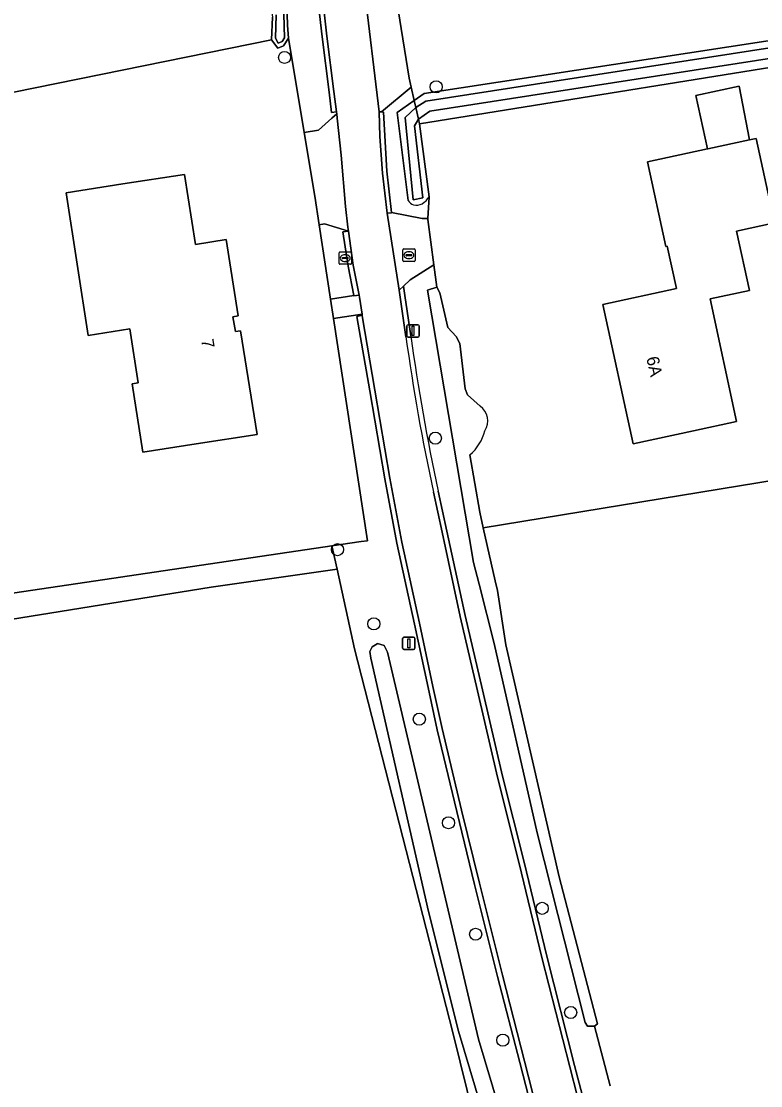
# Model space of a CAD drawing. Extents: x 162510 to 163918, y 388494 to 389774.
# Drawn here: x 163110.5 to 163170.3, y 389509.4 to 389595.4 of the extents above; entities that cross this region are included whole.
import ezdxf

# ---------------------------------------------------------------- set-up
doc = ezdxf.new("R2010")
doc.units = 0
for name, color, linetype in [('IMGEO_Afsluitpaal', 7, 'Continuous'), ('IMGEO_Boom', 7, 'Continuous'), ('IMGEO_Bouwland', 7, 'Continuous'), ('IMGEO_Brandkraan', 7, 'Continuous'), ('IMGEO_Erf', 7, 'Continuous'), ('IMGEO_Grasland_agrarisch', 7, 'Continuous'), ('IMGEO_Grasland_overig', 7, 'Continuous'), ('IMGEO_Groenvoorziening', 7, 'Continuous'), ('IMGEO_Oever', 7, 'Continuous'), ('IMGEO_Pand', 7, 'Continuous'), ('IMGEO_Pand_nummerreeks', 7, 'Continuous'), ('IMGEO_Rijbaan_lokaal_gesloten', 7, 'Continuous'), ('IMGEO_Rijbaan_lokaal_halfverhard', 7, 'Continuous'), ('IMGEO_Rijbaan_lokaal_open', 7, 'Continuous'), ('IMGEO_Rioolput', 7, 'Continuous'), ('IMGEO_Verkeersbordpaal', 7, 'Continuous'), ('IMGEO_Voetpad_open', 7, 'Continuous'), ('IMGEO_Waterloop', 7, 'Continuous')]:
    doc.layers.add(name, color=color, linetype=linetype)

msp = doc.modelspace()

# ---------------------------------------------------------------- linework, layer by layer
at = {"layer": 'IMGEO_Afsluitpaal'}
for p, q in [((163141.67, 389569.989), (163141.67, 389570.789)), ((163141.67, 389570.789), (163141.67, 389569.989)), ((163141.77, 389570.889), (163142.56, 389570.889)), ((163142.56, 389570.889), (163141.77, 389570.889)), ((163142.66, 389570.789), (163142.66, 389569.989)), ((163142.66, 389569.989), (163142.66, 389570.789)), ((163142.56, 389569.889), (163141.77, 389569.889)), ((163141.77, 389569.889), (163142.56, 389569.889))]:
    msp.add_line(p, q, dxfattribs=at)
msp.add_lwpolyline([(163142.09, 389570.764), (163142.24, 389570.764), (163142.24, 389570.014), (163142.09, 389570.014), (163142.09, 389570.764)], dxfattribs=at)
for centre, start, end in [((163141.77, 389570.789), 90, 180), ((163141.77, 389570.789), 90, 180), ((163142.56, 389570.789), 0, 90), ((163142.56, 389570.789), 360, 90), ((163141.77, 389569.989), 180, 270), ((163141.77, 389569.989), 180, 270), ((163142.56, 389569.989), 270, 0), ((163142.56, 389569.989), 270, 0)]:
    msp.add_arc(centre, 0.1, start, end, dxfattribs=at)
at = {"layer": 'IMGEO_Boom'}
for centre in [(163131.792, 389592.486), (163144.039, 389590.102), (163143.976, 389561.724), (163136.071, 389552.716), (163139, 389546.719), (163142.678, 389539.015), (163145.036, 389530.651), (163152.616, 389523.734), (163147.231, 389521.64), (163154.915, 389515.315), (163149.429, 389513.082)]:
    msp.add_circle(centre, 0.489, dxfattribs=at)
at = {"layer": 'IMGEO_Bouwland'}
msp.add_lwpolyline([(163081.431, 389571.505), (163036.713, 389569.507), (163036.922, 389568.463), (163034.881, 389568.403), (163038.378, 389551.874), (163041.389, 389540.203), (163045.337, 389519.553), (163052.453, 389485.976), (163058.338, 389486.211), (163065.742, 389486.647), (163069.57, 389487.128), (163075.689, 389486.797), (163079.708, 389487.203), (163100.597, 389488.503), (163120.69, 389490.419), (163133.944, 389491.791), (163150.042, 389494.851), (163145.402, 389513.689), (163141.615, 389528.41), (163137.44, 389544.706), (163136.047, 389551.139), (163125.857, 389549.679), (163092.552, 389544.325), (163089.105, 389543.766)], close=True, dxfattribs=at)
at = {"layer": 'IMGEO_Brandkraan'}
for p, q in [((163136.193, 389575.842), (163136.193, 389576.694)), ((163136.268, 389576.768), (163137.12, 389576.768)), ((163136.452, 389576.262), (163136.452, 389576.274)), ((163136.89, 389576.225), (163136.492, 389576.225)), ((163136.495, 389576.311), (163136.893, 389576.311)), ((163136.681, 389576.548), (163136.706, 389576.548)), ((163136.936, 389576.274), (163136.936, 389576.262)), ((163137.194, 389576.694), (163137.194, 389575.842)), ((163137.12, 389575.768), (163136.268, 389575.768)), ((163136.704, 389575.988), (163136.679, 389575.988))]:
    msp.add_line(p, q, dxfattribs=at)
for points in [[(163136.193, 389575.842), (163136.193, 389576.694)], [(163136.268, 389576.768), (163137.12, 389576.768)], [(163137.194, 389576.694), (163137.194, 389575.842)], [(163137.12, 389575.768), (163136.268, 389575.768)]]:
    msp.add_lwpolyline(points, dxfattribs=at)
for centre, radius, start, end in [((163136.27, 389576.692), 0.0765, 91.55205, 178.44795), ((163136.27, 389576.692), 0.0765, 91.55205, 178.44795), ((163136.492, 389576.271), 0.0403, 85.87752, 175.75265), ((163136.489, 389576.261), 0.0366, 178.93798, 274.71019), ((163136.893, 389576.268), 0.043, 264.86636, 352.45326), ((163136.897, 389576.273), 0.0386, 1.73085, 96.63898), ((163137.118, 389576.692), 0.0765, 1.55205, 88.44795), ((163137.118, 389576.692), 0.0765, 1.55205, 88.44795), ((163136.27, 389575.844), 0.0765, 181.55205, 268.44795), ((163136.27, 389575.844), 0.0765, 181.55205, 268.44795), ((163137.118, 389575.844), 0.0765, 271.55205, 358.44795), ((163137.118, 389575.844), 0.0765, 271.55205, 358.44795)]:
    msp.add_arc(centre, radius, start, end, dxfattribs=at)
for centre, major_axis, ratio, start_param, end_param in [((163136.68, 389576.268), (-0.387, 0.002), 0.722429, 4.712389, 7.853982), ((163136.705, 389576.268), (-0.39, 0.002), 0.717154, 1.570796, 4.712389)]:
    msp.add_ellipse(centre, major_axis=major_axis, ratio=ratio, start_param=start_param, end_param=end_param, dxfattribs=at)
at = {"layer": 'IMGEO_Erf'}
for points in [[(163146.776, 389560.376), (163147.559, 389555.746), (163147.85, 389554.465), (163200.467, 389563.084), (163209.162, 389564.768), (163211.121, 389565.147), (163210.605, 389567.919), (163211.953, 389568.291), (163210.994, 389575.221), (163208.337, 389574.958), (163206.563, 389587.551), (163202.535, 389611.212), (163185.361, 389663.193), (163183.199, 389670.235), (163182.976, 389670.167), (163189.652, 389648.224), (163198.162, 389622.433), (163197.592, 389622.245), (163189.08, 389648.043), (163182.625, 389669.258)], [(163137.903, 389615.424), (163141.862, 389590.82), (163142.032, 389590.074), (163142.273, 389589.016), (163143.068, 389589.581), (163201.297, 389598.514)], [(163201.383, 389596.57), (163184.867, 389593.87), (163185.299, 389590.871), (163179.29, 389590.006), (163178.867, 389592.946), (163142.703, 389587.125), (163143.463, 389581.223), (163143.376, 389579.476), (163143.371, 389579.381), (163143.861, 389575.722), (163144.086, 389573.93), (163144.327, 389573.462), (163144.976, 389570.666), (163145.666, 389569.948), (163145.953, 389569.366), (163146.391, 389565.701), (163146.582, 389565.22), (163147.61, 389564.317)]]:
    msp.add_lwpolyline(points, dxfattribs=at)
for points in [[(163135.605, 389553.015), (163137.969, 389553.364), (163138.48, 389553.44), (163135.741, 389571.383), (163135.501, 389572.957), (163134.583, 389578.971), (163134.232, 389581.269), (163133.369, 389586.428), (163132.097, 389594.034), (163131.711, 389593.428), (163131.252, 389593.229), (163130.743, 389593.913), (163099.541, 389587.586), (163095.489, 389586.851), (163101.431, 389547.961)], [(163165.975, 389585.088), (163165.041, 389589.4), (163168.544, 389590.158), (163169.364, 389585.821), (163169.917, 389585.941), (163171.396, 389579.109), (163168.327, 389578.445), (163169.361, 389573.666), (163166.185, 389572.979), (163168.33, 389563.071), (163164.841, 389562.316), (163159.954, 389561.258), (163157.514, 389572.532), (163163.455, 389573.818), (163162.715, 389577.238), (163162.598, 389577.213), (163161.121, 389584.037)], [(163123.699, 389583.033), (163124.584, 389577.378), (163127.071, 389577.78), (163128.042, 389571.601), (163127.606, 389571.529), (163127.811, 389570.327), (163128.24, 389570.406), (163129.579, 389562.03), (163124.639, 389561.261), (163120.343, 389560.591), (163119.481, 389566.125), (163119.966, 389566.201), (163119.288, 389570.554), (163115.922, 389570.03), (163114.129, 389581.542), (163118.724, 389582.259)]]:
    msp.add_lwpolyline(points, close=True, dxfattribs=at)
for centre, radius, start, end in [((163146.674, 389563.106), 1.531, 329.07671, 52.29416), ((163144.277, 389563.282), 3.833, 310.68755, 345.44493)]:
    msp.add_arc(centre, radius, start, end, dxfattribs=at)
at = {"layer": 'IMGEO_Grasland_agrarisch'}
for points in [[(162938.565, 389557.01), (163031.158, 389573.647), (163038.447, 389575.02), (163070.03, 389580.97), (163070.105, 389582.244), (163086.403, 389585.202), (163088.57, 389585.595), (163095.489, 389586.851), (163099.541, 389587.586), (163130.743, 389593.913), (163130.817, 389595.747)], [(163302.524, 389566.919), (163271.821, 389559.091), (163236.385, 389551.103), (163216.962, 389546.983), (163214.666, 389550.733), (163209.162, 389564.768), (163200.467, 389563.084), (163147.85, 389554.465), (163148.821, 389550.197), (163149, 389549.411), (163149.675, 389545.037), (163153.995, 389526.272), (163157.089, 389514.412), (163156.831, 389514.217), (163158.114, 389509.391)]]:
    msp.add_lwpolyline(points, dxfattribs=at)
at = {"layer": 'IMGEO_Grasland_overig'}
for points in [[(163131.988, 389595.99), (163132.038, 389595.088), (163132.097, 389594.034), (163133.369, 389586.428), (163134.528, 389586.609), (163135.61, 389587.567), (163136.009, 389587.92), (163135.989, 389588.081), (163135.592, 389588.034), (163135.386, 389589.682), (163134.821, 389594.161), (163134.055, 389600.943)], [(163158.114, 389509.391), (163156.831, 389514.217), (163156.275, 389514.216), (163156.074, 389514.497), (163152.198, 389529.843), (163148.741, 389545.124), (163147.511, 389549.919), (163147.062, 389551.67), (163143.333, 389573.672), (163144.086, 389573.93), (163143.861, 389575.722), (163141.938, 389574.52), (163141.403, 389574.011), (163141.519, 389573.248), (163141.99, 389569.979)], [(163144.208, 389557.436), (163144.911, 389554.204), (163146.381, 389547.392), (163147.778, 389541.399), (163149.397, 389534.42), (163151.145, 389527.457), (163152.981, 389519.863), (163155.232, 389511.027), (163155.857, 389508.596), (163156.989, 389504.138), (163156.58, 389504.033), (163157.183, 389501.707), (163158.324, 389500), (163159.376, 389498.426), (163161.227, 389491.733), (163161.913, 389489.267), (163162.855, 389482.594), (163163.024, 389482.162), (163163.358, 389482.274), (163163.998, 389480.594), (163165.073, 389477.775), (163167.095, 389472.533)]]:
    msp.add_lwpolyline(points, dxfattribs=at)
for points in [[(163136.943, 389578.443), (163135.007, 389579.042), (163134.583, 389578.971), (163135.501, 389572.957), (163137.394, 389573.255), (163136.94, 389575.625), (163136.492, 389578.38)], [(163094.295, 389546.906), (163092.161, 389546.361), (163092.552, 389544.325), (163125.857, 389549.679), (163136.047, 389551.139), (163135.605, 389553.015), (163101.431, 389547.961)]]:
    msp.add_lwpolyline(points, close=True, dxfattribs=at)
msp.add_arc((163317.446, 389594.538), 177.166, 187.96792, 192.08816, dxfattribs=at)
at = {"layer": 'IMGEO_Groenvoorziening'}
for points in [[(163142.273, 389589.016), (163142.032, 389590.074), (163139.61, 389588.085), (163139.784, 389588.073), (163140.065, 389583.296), (163140.425, 389579.967), (163142.916, 389579.473), (163143.376, 389579.476), (163143.463, 389581.223)], [(163141.774, 389580.916), (163140.89, 389588.033), (163142.273, 389589.016)], [(163151.769, 389507.502), (163150.791, 389511.273), (163149.005, 389518.231), (163147.151, 389525.659), (163145.708, 389531.564), (163144.129, 389538.161), (163143.391, 389541.585), (163142.292, 389546.693), (163140.869, 389553.236), (163139.895, 389558.423), (163138.683, 389565.543), (163137.641, 389571.561), (163138.065, 389571.647), (163138.051, 389571.74), (163135.741, 389571.383), (163138.48, 389553.44), (163137.969, 389553.364), (163135.605, 389553.015), (163136.047, 389551.139), (163137.44, 389544.706), (163141.615, 389528.41), (163145.402, 389513.689), (163150.042, 389494.851)], [(163150.884, 389497.95), (163150.592, 389498.209), (163150.426, 389498.501), (163149.969, 389500), (163145.858, 389513.801), (163143.43, 389523.472), (163138.762, 389543.954), (163138.691, 389544.487), (163138.872, 389544.867), (163139.265, 389545.116), (163139.306, 389545.142), (163139.838, 389544.96), (163140.112, 389544.424), (163147.453, 389513.152), (163151.385, 389500)]]:
    msp.add_lwpolyline(points, dxfattribs=at)
for centre, radius, start, end in [((163142.448, 389581.353), 0.804, 212.95584, 252.67475), ((163142.464, 389581.54), 0.988, 255.04432, 297.10059), ((163142.004, 389582.099), 1.702, 302.3257, 329.0151)]:
    msp.add_arc(centre, radius, start, end, dxfattribs=at)
at = {"layer": 'IMGEO_Oever'}
msp.add_lwpolyline([(163129.208, 389611.859), (163125.403, 389629.439), (163123.905, 389635.216), (163122.598, 389639.595), (163121.03, 389643.956), (163120.563, 389643.837), (163120.085, 389643.716), (163122.348, 389637.109), (163124.168, 389630.542), (163127.314, 389615.888), (163129.494, 389604.011), (163130.817, 389595.747), (163130.743, 389593.913), (163131.252, 389593.229), (163131.711, 389593.428), (163132.097, 389594.034), (163132.038, 389595.088), (163131.988, 389595.99)], close=True, dxfattribs=at)
for points in [[(163201.297, 389598.514), (163143.068, 389589.581), (163142.273, 389589.016), (163142.407, 389588.427), (163143.22, 389588.953), (163174.848, 389593.847), (163200.912, 389597.997)], [(163201.02, 389597.159), (163174.979, 389593.013), (163143.527, 389588.146), (163142.616, 389587.508), (163142.703, 389587.125), (163178.867, 389592.946), (163178.858, 389593.005), (163184.867, 389593.87), (163201.383, 389596.57), (163201.297, 389598.514)], [(163131.722, 389595.983), (163131.793, 389594.067), (163131.59, 389593.779), (163131.277, 389593.646), (163131.057, 389594.03), (163131.101, 389595.934)], [(163142.703, 389587.125), (163142.616, 389587.508), (163142.291, 389586.966), (163142.951, 389581.13), (163142.171, 389580.988), (163141.532, 389587.63), (163142.407, 389588.427), (163142.273, 389589.016), (163140.89, 389588.033), (163141.774, 389580.916)], [(163143.463, 389581.223), (163142.703, 389587.125)]]:
    msp.add_lwpolyline(points, dxfattribs=at)
for centre, radius, start, end in [((163142.448, 389581.353), 0.804, 212.95584, 252.67475), ((163142.464, 389581.54), 0.988, 255.04432, 297.10059), ((163142.004, 389582.099), 1.702, 302.3257, 329.0151)]:
    msp.add_arc(centre, radius, start, end, dxfattribs=at)
at = {"layer": 'IMGEO_Pand'}
for points in [[(163165.041, 389589.4), (163165.975, 389585.088), (163166.008, 389585.095), (163169.364, 389585.821), (163168.544, 389590.158)], [(163169.361, 389573.666), (163168.327, 389578.445), (163171.396, 389579.109), (163169.917, 389585.941), (163169.364, 389585.821), (163166.008, 389585.095), (163165.975, 389585.088), (163161.121, 389584.037), (163162.598, 389577.213), (163162.715, 389577.238), (163163.455, 389573.818), (163157.514, 389572.532), (163159.954, 389561.258), (163164.841, 389562.316), (163168.33, 389563.071), (163166.185, 389572.979)], [(163124.639, 389561.261), (163129.579, 389562.03), (163128.24, 389570.406), (163127.811, 389570.327), (163127.606, 389571.529), (163128.042, 389571.601), (163127.071, 389577.78), (163124.584, 389577.378), (163123.699, 389583.033), (163118.724, 389582.259), (163114.129, 389581.542), (163115.922, 389570.03), (163119.288, 389570.554), (163119.966, 389566.201), (163119.481, 389566.125), (163120.343, 389560.591)]]:
    msp.add_lwpolyline(points, close=True, dxfattribs=at)
at = {"layer": 'IMGEO_Rijbaan_lokaal_gesloten'}
for points in [[(163141.594, 389569.922), (163141.053, 389573.687), (163140.094, 389579.9), (163139.708, 389583.144), (163139.501, 389586.097), (163139.435, 389588.098), (163138.216, 389598.189), (163137.336, 389604.367), (163136.223, 389611.66), (163135.209, 389617.098), (163135.203, 389617.129), (163135.046, 389618.008), (163134.841, 389619.053), (163133.209, 389626.239)], [(163134.452, 389600.988), (163135.218, 389594.211), (163135.783, 389589.732), (163135.989, 389588.081), (163136.009, 389587.92), (163136.053, 389587.568), (163136.359, 389584.6), (163136.722, 389580.439), (163136.898, 389578.763), (163136.943, 389578.443), (163137.333, 389575.702), (163137.807, 389573.277), (163137.838, 389573.12), (163138.051, 389571.74), (163138.065, 389571.647), (163138.072, 389571.603), (163139.077, 389565.61), (163140.288, 389558.497), (163141.26, 389553.321), (163142.683, 389546.777), (163143.782, 389541.669), (163144.518, 389538.254), (163146.097, 389531.659), (163147.539, 389525.756), (163149.392, 389518.33), (163151.178, 389511.373), (163152.156, 389507.602)], [(163157.812, 389499.279), (163157.183, 389501.707), (163156.58, 389504.033), (163155.47, 389508.496), (163154.845, 389510.927), (163152.593, 389519.764), (163150.756, 389527.363), (163149.007, 389534.33), (163147.388, 389541.309), (163145.99, 389547.308), (163144.52, 389554.12), (163143.817, 389557.352)]]:
    msp.add_lwpolyline(points, dxfattribs=at)
msp.add_arc((163317.186, 389594.494), 177.303, 187.96607, 192.09201, dxfattribs=at)
at = {"layer": 'IMGEO_Rijbaan_lokaal_halfverhard'}
for points in [[(163129.617, 389624.501), (163130.847, 389619.293), (163131.78, 389614.905), (163132.904, 389609.133), (163133.517, 389605.201), (163134.055, 389600.943), (163134.821, 389594.161), (163135.386, 389589.682), (163135.592, 389588.034), (163135.989, 389588.081), (163135.783, 389589.732), (163135.218, 389594.211), (163134.452, 389600.988), (163133.914, 389605.251), (163133.299, 389609.195), (163132.173, 389614.981), (163131.238, 389619.376), (163130.006, 389624.593)], [(163141.403, 389574.011), (163141.053, 389573.687), (163141.594, 389569.922)], [(163141.99, 389569.979), (163141.519, 389573.248), (163141.403, 389574.011)], [(163152.156, 389507.602), (163151.178, 389511.373), (163149.392, 389518.33), (163147.539, 389525.756), (163146.097, 389531.659), (163144.518, 389538.254), (163143.782, 389541.669), (163142.683, 389546.777), (163141.26, 389553.321), (163140.288, 389558.497), (163139.077, 389565.61), (163138.072, 389571.603), (163138.065, 389571.647), (163137.641, 389571.561), (163138.683, 389565.543), (163139.895, 389558.423), (163140.869, 389553.236), (163142.292, 389546.693), (163143.391, 389541.585), (163144.129, 389538.161), (163145.708, 389531.564), (163147.151, 389525.659), (163149.005, 389518.231), (163150.791, 389511.273), (163151.769, 389507.502)], [(163143.817, 389557.352), (163144.52, 389554.12), (163145.99, 389547.308), (163147.388, 389541.309), (163149.007, 389534.33), (163150.756, 389527.363), (163152.593, 389519.764), (163154.845, 389510.927), (163155.47, 389508.496), (163156.58, 389504.033), (163156.989, 389504.138), (163155.857, 389508.596), (163155.232, 389511.027), (163152.981, 389519.863), (163151.145, 389527.457), (163149.397, 389534.42), (163147.778, 389541.399), (163146.381, 389547.392), (163144.911, 389554.204), (163144.208, 389557.436)]]:
    msp.add_lwpolyline(points, dxfattribs=at)
for points in [[(163139.784, 389588.073), (163139.61, 389588.085), (163139.435, 389588.098), (163139.501, 389586.097), (163139.708, 389583.144), (163140.094, 389579.9), (163140.429, 389579.931), (163140.425, 389579.967), (163140.065, 389583.296)], [(163136.943, 389578.443), (163136.492, 389578.38), (163136.94, 389575.625), (163137.394, 389573.255), (163137.398, 389573.232), (163137.807, 389573.277), (163137.333, 389575.702)]]:
    msp.add_lwpolyline(points, close=True, dxfattribs=at)
for centre, radius, start, end in [((163317.186, 389594.494), 177.303, 187.96607, 192.09201), ((163317.446, 389594.538), 177.166, 187.96792, 192.08816)]:
    msp.add_arc(centre, radius, start, end, dxfattribs=at)
at = {"layer": 'IMGEO_Rijbaan_lokaal_open'}
for points in [[(163137.903, 389615.424), (163137.442, 389617.529), (163135.597, 389617.199), (163135.203, 389617.129), (163135.209, 389617.098), (163136.223, 389611.66), (163137.336, 389604.367), (163138.216, 389598.189), (163139.435, 389588.098), (163139.61, 389588.085), (163142.032, 389590.074), (163141.862, 389590.82)], [(163136.009, 389587.92), (163135.61, 389587.567), (163134.528, 389586.609), (163133.369, 389586.428), (163134.232, 389581.269), (163134.583, 389578.971), (163135.007, 389579.042), (163136.943, 389578.443), (163136.898, 389578.763), (163136.722, 389580.439), (163136.359, 389584.6), (163136.053, 389587.568)], [(163143.371, 389579.381), (163143.376, 389579.476), (163142.916, 389579.473), (163140.425, 389579.967), (163140.429, 389579.931), (163140.094, 389579.9), (163141.053, 389573.687), (163141.403, 389574.011), (163141.938, 389574.52), (163143.861, 389575.722)]]:
    msp.add_lwpolyline(points, close=True, dxfattribs=at)
at = {"layer": 'IMGEO_Rioolput'}
for p, q in [((163141.341, 389576.082), (163141.341, 389576.934)), ((163141.416, 389577.008), (163142.268, 389577.008)), ((163141.6, 389576.502), (163141.6, 389576.514)), ((163142.038, 389576.465), (163141.64, 389576.465)), ((163141.643, 389576.551), (163142.041, 389576.551)), ((163141.852, 389576.228), (163141.827, 389576.228)), ((163141.829, 389576.788), (163141.854, 389576.788)), ((163142.084, 389576.514), (163142.084, 389576.502)), ((163142.342, 389576.934), (163142.342, 389576.082)), ((163142.268, 389576.008), (163141.416, 389576.008))]:
    msp.add_line(p, q, dxfattribs=at)
for points in [[(163141.341, 389576.082), (163141.341, 389576.934)], [(163141.416, 389577.008), (163142.268, 389577.008)], [(163142.342, 389576.934), (163142.342, 389576.082)], [(163142.268, 389576.008), (163141.416, 389576.008)]]:
    msp.add_lwpolyline(points, dxfattribs=at)
for centre, radius, start, end in [((163141.418, 389576.932), 0.0765, 91.55205, 178.44795), ((163141.418, 389576.932), 0.0765, 91.55205, 178.44795), ((163141.64, 389576.511), 0.0403, 85.87752, 175.75265), ((163141.637, 389576.501), 0.0366, 178.93798, 274.71019), ((163142.041, 389576.508), 0.043, 264.86636, 352.45326), ((163142.045, 389576.513), 0.0386, 1.73085, 96.63898), ((163142.266, 389576.932), 0.0765, 1.55205, 88.44795), ((163142.266, 389576.932), 0.0765, 1.55205, 88.44795), ((163141.418, 389576.084), 0.0765, 181.55205, 268.44795), ((163141.418, 389576.084), 0.0765, 181.55205, 268.44795), ((163142.266, 389576.084), 0.0765, 271.55205, 358.44795), ((163142.266, 389576.084), 0.0765, 271.55205, 358.44795)]:
    msp.add_arc(centre, radius, start, end, dxfattribs=at)
for centre, major_axis, ratio, start_param, end_param in [((163141.828, 389576.508), (-0.387, 0.002), 0.722429, 4.712389, 7.853982), ((163141.853, 389576.508), (-0.39, 0.002), 0.717154, 1.570796, 4.712389)]:
    msp.add_ellipse(centre, major_axis=major_axis, ratio=ratio, start_param=start_param, end_param=end_param, dxfattribs=at)
at = {"layer": 'IMGEO_Verkeersbordpaal'}
for p, q in [((163141.332, 389544.746), (163141.332, 389545.546)), ((163141.332, 389545.546), (163141.332, 389544.746)), ((163141.432, 389545.646), (163142.222, 389545.646)), ((163142.222, 389545.646), (163141.432, 389545.646)), ((163142.322, 389545.546), (163142.322, 389544.746)), ((163142.322, 389544.746), (163142.322, 389545.546)), ((163142.222, 389544.646), (163141.432, 389544.646)), ((163141.432, 389544.646), (163142.222, 389544.646))]:
    msp.add_line(p, q, dxfattribs=at)
msp.add_lwpolyline([(163141.752, 389545.521), (163141.902, 389545.521), (163141.902, 389544.771), (163141.752, 389544.771), (163141.752, 389545.521)], dxfattribs=at)
for centre, start, end in [((163141.432, 389545.546), 90, 180), ((163141.432, 389545.546), 90, 180), ((163142.222, 389545.546), 0, 90), ((163142.222, 389545.546), 360, 90), ((163141.432, 389544.746), 180, 270), ((163141.432, 389544.746), 180, 270), ((163142.222, 389544.746), 270, 0), ((163142.222, 389544.746), 270, 0)]:
    msp.add_arc(centre, 0.1, start, end, dxfattribs=at)
at = {"layer": 'IMGEO_Voetpad_open'}
msp.add_lwpolyline([(163137.807, 389573.277), (163137.398, 389573.232), (163137.394, 389573.255), (163135.501, 389572.957), (163135.741, 389571.383), (163138.051, 389571.74), (163137.838, 389573.12)], close=True, dxfattribs=at)
at = {"layer": 'IMGEO_Waterloop'}
for points in [[(163200.912, 389597.997), (163174.848, 389593.847), (163143.22, 389588.953), (163142.407, 389588.427), (163142.616, 389587.508), (163143.527, 389588.146), (163174.979, 389593.013), (163201.02, 389597.159)], [(163131.101, 389595.934), (163131.057, 389594.03), (163131.277, 389593.646), (163131.59, 389593.779), (163131.793, 389594.067), (163131.722, 389595.983)], [(163147.61, 389564.317), (163146.582, 389565.22), (163146.391, 389565.701), (163145.953, 389569.366), (163145.666, 389569.948), (163144.976, 389570.666), (163144.327, 389573.462), (163144.086, 389573.93), (163143.333, 389573.672), (163147.062, 389551.67), (163147.511, 389549.919), (163148.741, 389545.124), (163152.198, 389529.843), (163156.074, 389514.497), (163156.275, 389514.216), (163156.831, 389514.217), (163157.089, 389514.412), (163153.995, 389526.272), (163149.675, 389545.037), (163149, 389549.411), (163148.821, 389550.197), (163147.85, 389554.465), (163147.559, 389555.746), (163146.776, 389560.376)], [(163140.112, 389544.424), (163139.838, 389544.96), (163139.306, 389545.142), (163139.265, 389545.116), (163138.872, 389544.867), (163138.691, 389544.487), (163138.762, 389543.954), (163143.43, 389523.472), (163145.858, 389513.801), (163149.969, 389500), (163150.426, 389498.501), (163150.592, 389498.209), (163150.884, 389497.95)], [(163151.645, 389498.06), (163151.767, 389498.443), (163151.743, 389498.803), (163151.385, 389500), (163147.453, 389513.152), (163140.112, 389544.424)]]:
    msp.add_lwpolyline(points, dxfattribs=at)
msp.add_lwpolyline([(163142.616, 389587.508), (163142.407, 389588.427), (163141.532, 389587.63), (163142.171, 389580.988), (163142.951, 389581.13), (163142.291, 389586.966)], close=True, dxfattribs=at)
for centre, radius, start, end in [((163146.674, 389563.106), 1.531, 329.07671, 52.29416), ((163144.277, 389563.282), 3.833, 310.68755, 345.44493)]:
    msp.add_arc(centre, radius, start, end, dxfattribs=at)

# ---------------------------------------------------------------- texts
at = {"layer": 'IMGEO_Pand_nummerreeks'}
for s, rotation, p in [('7', 279.04771, (163125.042, 389569.662)), ('6A', 282.20952, (163161.026, 389568.214))]:
    msp.add_text(s, height=1, rotation=rotation, dxfattribs=at).set_placement(p)

doc.saveas('drawing.dxf')
